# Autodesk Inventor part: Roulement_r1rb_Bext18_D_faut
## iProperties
Created: 2011-10
Part Number: Roulement_r1rb_Bext18_D_faut
Document SubType Name: Modeling
Designer: Bruno
Author: Bruno
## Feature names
1. Base1
